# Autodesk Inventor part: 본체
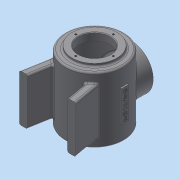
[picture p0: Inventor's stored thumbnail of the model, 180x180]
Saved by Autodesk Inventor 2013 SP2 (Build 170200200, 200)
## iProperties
Created: 2015-01
Part Number: 본체
Material: 일반
Document SubType Name: Modeling
Designer: dgall
Density: 1 g/cm^3
Author: dgall
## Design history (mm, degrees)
sketch "스케치1"
  geometry: C1 r 50 at (0, 0); C2 r 38 at (0, 0); 1 further point
  constraints: 2 centre point, 1 coincident
  dimensions: "d0" = 100 diameter of C1; "d2" = 76 diameter of C2
extrude "돌출1" new body sketch "스케치1" distance "d3" = 57; taper "d4" = 0 deg
extrude "돌출2" join sketch "스케치1" distance "d5" = 62; taper "d6" = 0 deg
extrude "돌출3" join sketch "스케치1" distance "d7" = 55; taper "d8" = 0 deg
extrude "돌출4" join sketch "스케치1" distance "d9" = 60; taper "d10" = 0 deg
node "작업 평면1"
sketch "스케치2"
  geometry: L1 (-39.336, -30.865)-(-48, -80); L2 (-48, -80)-(-34, -80); L3 (-34, -80)-(-27.282, -41.901); L4 (39.336, -30.865)-(48, -80); L5 (48, -80)-(34, -80); L6 (34, -80)-(27.282, -41.901); A1 r 50 centre (0, 0) between (-39.336, -30.865) and (-27.282, -41.901) reference; 1 further point
  constraints: 12 end point, 4 point on circle, 3 equal length, 2 parallel, 1 collinear, 1 horizontal, 1 horizontal alignment
  dimensions: "d11" = 80 vertical distance of L1.end point (0, 0); "d12" = 80 deg angle of L3 L2; "d13" = 14 distance of L1.end L2.end; "d14" = 96 distance of L4.end L1.end
extrude "돌출5" join sketch "스케치2" stored distance "d15" = 80; taper "d16" = 0 deg
node "작업 평면2"
sketch "스케치3"
  geometry: C1 r 38 at (-48, -41); 1 further point
  constraints: 1 centre point, 1 coincident
  dimensions: "d18" = 76 diameter of C1
extrude "돌출6" join sketch "스케치3" stored distance "d20" = 80; taper "d21" = 0 deg
sketch "스케치4"
  geometry: L1 (-38, -60)-(38, -60) reference; L2 (38, 62)-(-38, 62) reference; L3 (0, -60)-(0, 62); L4 (0, -60)-(27, -60); L5 (27, -60)-(27, -48); L6 (27, -48)-(45, -48); L7 (45, -48)-(45, 49); L8 (45, 49)-(27, 49); L9 (27, 49)-(27, 62); L10 (27, 62)-(0, 62); 1 further point
  constraints: 16 end point, 3 perpendicular, 2 midpoint, 2 parallel, 2 point on line, 1 collinear, 1 vertical alignment
  dimensions: "d22" = 12 distance from line of L5.end L4; "d24" = 13 vertical distance of L7.end L9.end; "d25" = 54 diameter of L4.end L3; "d26" = 90 diameter of L7 L3
revolve "회전1" sketch "스케치4" stored, may be unused: angle "d27" = 90 deg
hole "구멍1" diameter "d30" = 54; stored, may be unused: countersink angle "d34" = 90 deg, drill point angle "d36" = 118 deg; dims "d28" = 10, "d29" = 10, "d31" = 6, "d32" = 4, "d33" = 2, "d35" = 8
fillet "모깎기1" dims "d37" = 3
fillet "모깎기2" dims "d38" = 3
fillet "모깎기3" dims "d39" = 3
chamfer "모따기1" distance "d40" = 1; stored, may be unused: second distance "d41" = 2, angle "d42" = 45 deg
fillet "모깎기4" dims "d43" = 3
sketch "스케치5"
  geometry: C1 r 38 at (0, 0) reference; 1 further point
  constraints: 1 vertical alignment
  dimensions: "d44" = 32 distance of point (0, 32) C1.centre
hole "구멍2" sketch "스케치5" at (0, 32) diameter "d45" = 3.242; stored, may be unused: countersink angle "d49" = 90 deg, drill point angle "d51" = 118 deg; dims "d46" = 8, "d47" = 4, "d48" = 2, "d50" = 10
sketch "스케치6"
  geometry: C1 r 38 at (0, 0) reference; 1 further point
  constraints: 1 vertical alignment
  dimensions: "d55" = 32 distance of C1.centre point (0, 32)
hole "구멍3" sketch "스케치6" at (0, 32) diameter "d56" = 3.242; stored, may be unused: countersink angle "d60" = 90 deg, drill point angle "d62" = 118 deg; dims "d57" = 8, "d58" = 4, "d59" = 2, "d61" = 10
node "작업 평면3"
sketch "스케치7"
  geometry: L1 (6, 27)-(-6, 27); L2 (-6, 27)-(-6, -27); L3 (-6, -27)-(6, -27); L4 (6, -27)-(6, 27); 3 further points
  constraints: 8 end point, 2 midpoint, 2 parallel, 1 horizontal, 1 horizontal alignment, 1 perpendicular, 1 vertical alignment
  dimensions: "d67" = 54 distance of L3.end L1.start; "d69" = 12 distance of L1.start L1.end
extrude "돌출7" join sketch "스케치7" stored distance "d70" = 80; taper "d71" = 0 deg
sketch "스케치8"
  geometry: L1 (-27, 6)-(-27, -6) reference; L2 (27, 6)-(-27, 6) reference; 4 further points
  constraints: 2 midpoint, 1 horizontal alignment, 1 vertical alignment, 1 other
feature "엠보싱1" sketch "스케치8" dims "d72" = 0.5, "d73" = 0
node "솔리드1"
pattern_circular "원형 패턴1" dims angle "d53" = 360 deg
mirror "대칭1"
pattern_circular "원형 패턴2" dims angle "d64" = 360 deg
other parameters: "d17" = -142, "d66" = 52
